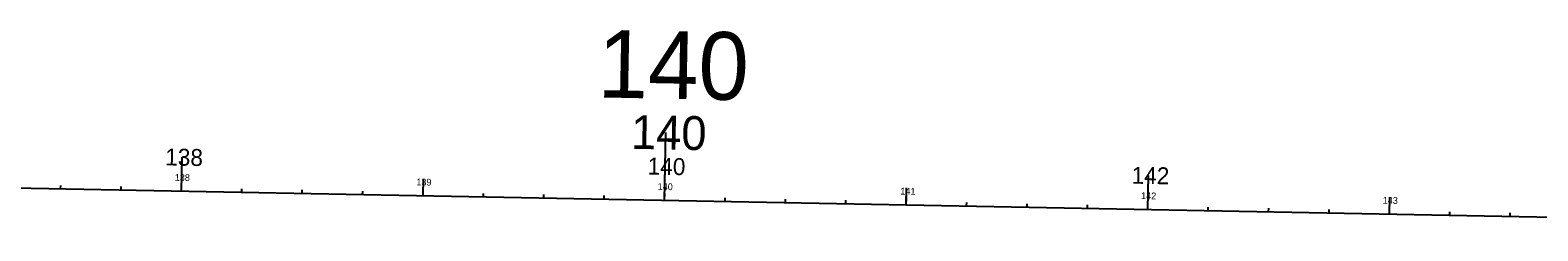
# Model space of a CAD drawing. Extents: x 586268 to 602442, y 101017 to 226037.
# Drawn here: x 593088 to 593712, y 154427 to 154510 of the extents above; entities that cross this region are included whole.
import ezdxf

# ---------------------------------------------------------------- set-up
doc = ezdxf.new("R2010")
doc.units = 0
for name, color, linetype in [('E_ALI_100', 7, 'Continuous'), ('Level 24', 7, 'Continuous'), ('Level 32', 7, 'Continuous'), ('P_ALI_100', 7, 'Continuous'), ('P_ALI_100_Sta', 7, 'Continuous'), ('P_ALI_100_Tic', 7, 'Continuous'), ('P_ALI_50', 7, 'Continuous'), ('P_ALI_50_PIData', 7, 'Continuous'), ('P_ALI_50_Sta', 7, 'Continuous'), ('P_ALI_50_Tic', 7, 'Continuous')]:
    doc.layers.add(name, color=color, linetype=linetype)

msp = doc.modelspace()

# ---------------------------------------------------------------- linework, layer by layer
at = {"layer": 'E_ALI_100'}
msp.add_line((591555.8, 154473.93), (594020.07, 154427.28), dxfattribs=at)
at = {"layer": 'Level 24'}
for points in [[(593100.48, 154446.09), (593100.46, 154444.69)], [(593125.48, 154445.61), (593125.45, 154444.21)], [(593150.5, 154446.54), (593150.45, 154443.74)], [(593175.47, 154444.67), (593175.44, 154443.27)], [(593200.46, 154444.19), (593200.44, 154442.79)], [(593225.46, 154443.72), (593225.43, 154442.32)], [(593250.48, 154444.65), (593250.43, 154441.85)], [(593275.45, 154442.77), (593275.42, 154441.37)], [(593300.45, 154442.3), (593300.42, 154440.9)], [(593325.44, 154441.83), (593325.42, 154440.43)], [(593350.46, 154442.75), (593350.41, 154439.95)], [(593375.43, 154440.88), (593375.41, 154439.48)], [(593450.45, 154440.86), (593450.39, 154438.06)], [(593400.43, 154440.41), (593400.4, 154439.01)], [(593425.42, 154439.93), (593425.4, 154438.53)], [(593475.42, 154438.99), (593475.39, 154437.59)], [(593500.41, 154438.51), (593500.38, 154437.11)], [(593525.41, 154438.04), (593525.38, 154436.64)], [(593550.43, 154438.97), (593550.38, 154436.17)], [(593575.4, 154437.1), (593575.37, 154435.7)], [(593600.39, 154436.62), (593600.37, 154435.22)], [(593625.39, 154436.15), (593625.36, 154434.75)], [(593650.41, 154437.08), (593650.36, 154434.28)], [(593675.38, 154435.2), (593675.35, 154433.8)], [(593700.38, 154434.73), (593700.35, 154433.33)]]:
    msp.add_lwpolyline(points, dxfattribs=at)
at = {"layer": 'P_ALI_100'}
msp.add_line((591555.8, 154473.93), (594020.07, 154427.28), dxfattribs=at)
at = {"layer": 'P_ALI_100_Sta'}
for points in [[(593350.94, 154467.95), (593350.41, 154439.95)], [(593150.71, 154457.74), (593150.45, 154443.74)], [(593550.64, 154450.17), (593550.38, 154436.17)]]:
    msp.add_lwpolyline(points, dxfattribs=at)
at = {"layer": 'P_ALI_100_Tic'}
for points in [[(593350.68, 154453.95), (593350.41, 154439.95)], [(593150.58, 154450.74), (593150.45, 154443.74)], [(593250.56, 154448.85), (593250.43, 154441.85)], [(593450.53, 154445.06), (593450.39, 154438.06)], [(593550.51, 154443.17), (593550.38, 154436.17)], [(593650.49, 154441.27), (593650.36, 154434.28)]]:
    msp.add_lwpolyline(points, dxfattribs=at)
at = {"layer": 'P_ALI_50'}
msp.add_line((591555.8, 154473.93), (594020.07, 154427.28), dxfattribs=at)
at = {"layer": 'P_ALI_50_Sta'}
msp.add_line((591555.8, 154473.93), (594020.07, 154427.28), dxfattribs=at)
at = {"layer": 'P_ALI_50_Tic'}
for points in [[(593150.58, 154450.74), (593150.45, 154443.74)], [(593350.54, 154446.95), (593350.41, 154439.95)], [(593250.5, 154445.35), (593250.43, 154441.85)], [(593450.46, 154441.56), (593450.39, 154438.06)], [(593550.51, 154443.17), (593550.38, 154436.17)], [(593650.42, 154437.78), (593650.36, 154434.28)]]:
    msp.add_lwpolyline(points, dxfattribs=at)

# ---------------------------------------------------------------- texts
at = {"layer": 'Level 32'}
for s, p in [('138', (593147.79, 154447.99)), ('139', (593247.78, 154446.1)), ('140', (593347.64, 154444.21)), ('141', (593448.09, 154442.31)), ('142', (593547.72, 154440.42)), ('143', (593647.7, 154438.53))]:
    msp.add_text(s, height=2.8, rotation=358.91546, dxfattribs=at).set_placement(p)
at = {"layer": 'P_ALI_100_Sta'}
msp.add_text('140', height=14, rotation=358.91546, dxfattribs=at).set_placement((593336.54, 154461.22))
at = {"layer": 'P_ALI_50_PIData'}
msp.add_text('140', height=28, rotation=358.91546, dxfattribs=at).set_placement((593322.66, 154482.49))
at = {"layer": 'P_ALI_50_Sta'}
for s, p in [('138', (593143.81, 154454.37)), ('140', (593343.47, 154450.59)), ('142', (593543.74, 154446.8))]:
    msp.add_text(s, height=7, rotation=358.91546, dxfattribs=at).set_placement(p)

doc.saveas('drawing.dxf')
